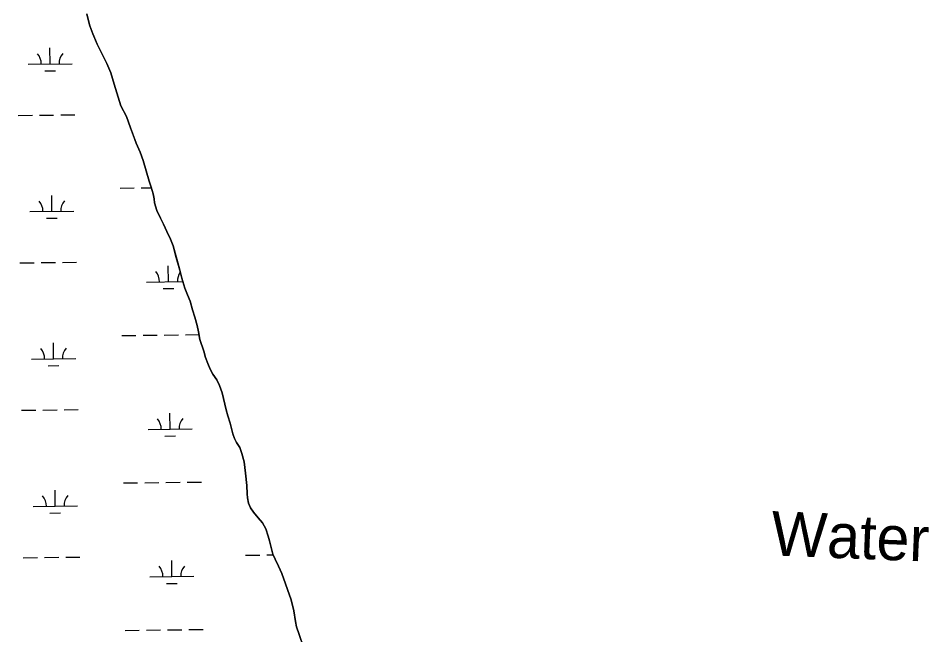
# Model space of a CAD drawing. Extents: x 3678539 to 3716648, y 451386 to 477139.
# Drawn here: x 3688551 to 3690606, y 458475 to 459867 of the extents above; entities that cross this region are included whole.
import ezdxf

# ---------------------------------------------------------------- set-up
doc = ezdxf.new("R2010")
doc.units = 0
for name, color, linetype in [('V-RIVR-IDEN', 7, 'Continuous'), ('V-TOPO-SHOR', 7, 'Continuous'), ('V-WETL-SWMP', 7, 'Continuous')]:
    doc.layers.add(name, color=color, linetype=linetype)

msp = doc.modelspace()

# ---------------------------------------------------------------- linework, layer by layer
at = {"layer": 'V-TOPO-SHOR'}
msp.add_lwpolyline([(3689195.2, 458447.5), (3689185, 458476.1), (3689179.4, 458493), (3689176.6, 458505), (3689173.4, 458529.2), (3689167.4, 458553.9), (3689146, 458613.5), (3689138.6, 458630.1), (3689130.7, 458645.8), (3689125.6, 458657.2), (3689120.8, 458675.4), (3689118.3, 458687.4), (3689115.3, 458697.8), (3689109.7, 458714.5), (3689102.5, 458728), (3689092.2, 458739.5), (3689081.9, 458751.8), (3689075.2, 458761.7), (3689070.9, 458772.1), (3689068.1, 458784.1), (3689067.9, 458793.4), (3689066.8, 458812.4), (3689063.6, 458839.9), (3689061.2, 458865.9), (3689055.9, 458884.6), (3689050.8, 458897.9), (3689043.6, 458909.4), (3689039.3, 458918.2), (3689035.2, 458929.2), (3689032.7, 458941.1), (3689029.4, 458952.8), (3689024.1, 458969.8), (3689020.5, 458982.8), (3689011.2, 459021.5), (3689004.9, 459037.9), (3688999, 459050.7), (3688990.2, 459063.5), (3688984.4, 459074.4), (3688978.7, 459087.2), (3688973.9, 459101), (3688969.6, 459115.5), (3688961, 459141.8), (3688957.7, 459159), (3688954.7, 459173), (3688949.7, 459192.3), (3688944.3, 459208.9), (3688938.8, 459227.9), (3688933.4, 459242.2), (3688927.3, 459257.8), (3688919.9, 459280.2), (3688915.4, 459298.2), (3688906.3, 459331.7), (3688900.5, 459353.3), (3688894.9, 459368.4), (3688886.7, 459385.6), (3688878.8, 459402), (3688872.1, 459415.3), (3688863.7, 459433), (3688858.6, 459450.2), (3688857.7, 459458.8), (3688855.7, 459470.7), (3688851.1, 459485.5), (3688846.3, 459498.8), (3688832.6, 459545.6), (3688826, 459564.1), (3688817.1, 459584.4), (3688810.2, 459603.7), (3688804.6, 459619.6), (3688795.4, 459644.6), (3688782.4, 459669.1), (3688767.2, 459718), (3688759.6, 459743.2), (3688750.6, 459764.3), (3688742, 459782.5), (3688728.9, 459808.1), (3688723.6, 459820.8), (3688719, 459831.5), (3688712.3, 459849.7), (3688708.8, 459863.5), (3688705.5, 459876.8)], dxfattribs=at)
at = {"layer": 'V-WETL-SWMP'}
for p, q in [((3688705.5, 459876.8), (3688712.3, 459849.7)), ((3688712.3, 459849.7), (3688719, 459831.5)), ((3688719, 459831.5), (3688728.9, 459808.1)), ((3688622.9, 459763.5), (3688622.5, 459799.5)), ((3688728.9, 459808.1), (3688742, 459782.5)), ((3688742, 459782.5), (3688750.6, 459764.3)), ((3688573, 459762.9), (3688672.9, 459764.1)), ((3688611.1, 459748), (3688635.1, 459748.2)), ((3688750.6, 459764.3), (3688759.6, 459743.2)), ((3688759.6, 459743.2), (3688767.2, 459718)), ((3688767.2, 459718), (3688782.4, 459669.1)), ((3688782.4, 459669.1), (3688795.4, 459644.6)), ((3688550.9, 459647.3), (3688582.9, 459647.6)), ((3688598.9, 459647.8), (3688630.9, 459648.2)), ((3688646.9, 459648.4), (3688678.9, 459648.7)), ((3688795.4, 459644.6), (3688804.6, 459619.6)), ((3688804.6, 459619.6), (3688817.1, 459584.4)), ((3688817.1, 459584.4), (3688826, 459564.1)), ((3688826, 459564.1), (3688832.6, 459545.6)), ((3688832.6, 459545.6), (3688846.3, 459498.8)), ((3688780.8, 459483.4), (3688812.8, 459483.7)), ((3688828.8, 459483.9), (3688851.5, 459484.2)), ((3688846.3, 459498.8), (3688851.1, 459485.5)), ((3688851.1, 459485.5), (3688855.7, 459470.7)), ((3688626.8, 459430.9), (3688626.4, 459466.9)), ((3688855.7, 459470.7), (3688857.7, 459458.8)), ((3688857.7, 459458.8), (3688858.6, 459450.2)), ((3688858.6, 459450.2), (3688863.7, 459433)), ((3688576.8, 459430.3), (3688676.8, 459431.4)), ((3688863.7, 459433), (3688872.1, 459415.3)), ((3688614.9, 459415.3), (3688638.9, 459415.6)), ((3688872.1, 459415.3), (3688878.8, 459402)), ((3688878.8, 459402), (3688886.7, 459385.6)), ((3688886.7, 459385.6), (3688894.9, 459368.4)), ((3688894.9, 459368.4), (3688900.5, 459353.3)), ((3688900.5, 459353.3), (3688915.4, 459298.2)), ((3688650.7, 459315.7), (3688682.7, 459316.1)), ((3688554.7, 459314.6), (3688586.7, 459315)), ((3688602.7, 459315.1), (3688634.7, 459315.5)), ((3688890.1, 459272), (3688889.6, 459308)), ((3688915.4, 459298.2), (3688919.9, 459280.2)), ((3688919.9, 459280.2), (3688927.3, 459257.8)), ((3688840.1, 459271.4), (3688922.5, 459272.4)), ((3688878.2, 459256.5), (3688902.2, 459256.7)), ((3688927.3, 459257.8), (3688933.4, 459242.2)), ((3688933.4, 459242.2), (3688938.8, 459227.9)), ((3688938.8, 459227.9), (3688944.3, 459208.9)), ((3688944.3, 459208.9), (3688949.7, 459192.3)), ((3688949.7, 459192.3), (3688954.7, 459173)), ((3688954.7, 459173), (3688957.7, 459159)), ((3688832.6, 459151.3), (3688864.6, 459151.6)), ((3688880.6, 459151.8), (3688912.6, 459152.2)), ((3688928.6, 459152.4), (3688958.9, 459152.7)), ((3688957.7, 459159), (3688961, 459141.8)), ((3688630.6, 459098.2), (3688630.2, 459134.2)), ((3688784.6, 459150.7), (3688816.6, 459151.1)), ((3688961, 459141.8), (3688969.6, 459115.5)), ((3688969.6, 459115.5), (3688973.9, 459101)), ((3688580.6, 459097.6), (3688680.6, 459098.8)), ((3688973.9, 459101), (3688978.7, 459087.2)), ((3688618.8, 459082.6), (3688642.8, 459082.9)), ((3688978.7, 459087.2), (3688984.4, 459074.4)), ((3688984.4, 459074.4), (3688990.2, 459063.5)), ((3688990.2, 459063.5), (3688999, 459050.7)), ((3688999, 459050.7), (3689004.9, 459037.9)), ((3689004.9, 459037.9), (3689011.2, 459021.5)), ((3689011.2, 459021.5), (3689020.5, 458982.8)), ((3688558.5, 458981.9), (3688590.5, 458982.3)), ((3688606.5, 458982.5), (3688638.5, 458982.9)), ((3688654.5, 458983), (3688686.5, 458983.4)), ((3688893.9, 458939.4), (3688893.5, 458975.4)), ((3689020.5, 458982.8), (3689024.1, 458969.8)), ((3689024.1, 458969.8), (3689029.4, 458952.8)), ((3689029.4, 458952.8), (3689032.7, 458941.1)), ((3688843.9, 458938.8), (3688943.9, 458939.9)), ((3689032.7, 458941.1), (3689035.2, 458929.2)), ((3689035.2, 458929.2), (3689039.3, 458918.2)), ((3688882.1, 458923.8), (3688906, 458924.1)), ((3689039.3, 458918.2), (3689043.6, 458909.4)), ((3689043.6, 458909.4), (3689050.8, 458897.9)), ((3689050.8, 458897.9), (3689055.9, 458884.6)), ((3689055.9, 458884.6), (3689061.2, 458865.9)), ((3689061.2, 458865.9), (3689063.6, 458839.9)), ((3689063.6, 458839.9), (3689066.8, 458812.4)), ((3688788.4, 458818.1), (3688820.4, 458818.4)), ((3688836.4, 458818.6), (3688868.4, 458819)), ((3688884.4, 458819.2), (3688916.4, 458819.5)), ((3688932.4, 458819.7), (3688964.4, 458820.1)), ((3689066.8, 458812.4), (3689067.9, 458793.4)), ((3688634.4, 458765.6), (3688634, 458801.6)), ((3689067.9, 458793.4), (3689068.1, 458784.1)), ((3689068.1, 458784.1), (3689070.9, 458772.1)), ((3688584.4, 458765), (3688684.4, 458766.1)), ((3689070.9, 458772.1), (3689075.2, 458761.7)), ((3689075.2, 458761.7), (3689081.9, 458751.8)), ((3688622.6, 458750), (3688646.6, 458750.3)), ((3689081.9, 458751.8), (3689092.2, 458739.5)), ((3689092.2, 458739.5), (3689102.5, 458728)), ((3689102.5, 458728), (3689109.7, 458714.5)), ((3689109.7, 458714.5), (3689115.3, 458697.8)), ((3689115.3, 458697.8), (3689118.3, 458687.4)), ((3689118.3, 458687.4), (3689120.8, 458675.4)), ((3689120.8, 458675.4), (3689125.6, 458657.2)), ((3688562.3, 458649.3), (3688594.3, 458649.7)), ((3688610.3, 458649.8), (3688642.3, 458650.2)), ((3688658.3, 458650.4), (3688690.3, 458650.8)), ((3688897.7, 458606.7), (3688897.3, 458642.7)), ((3689064.2, 458655.1), (3689096.2, 458655.4)), ((3689112.2, 458655.6), (3689126.2, 458655.8)), ((3689125.6, 458657.2), (3689130.7, 458645.8)), ((3689130.7, 458645.8), (3689138.6, 458630.1)), ((3689138.6, 458630.1), (3689146, 458613.5)), ((3688847.7, 458606.1), (3688947.7, 458607.3)), ((3689146, 458613.5), (3689167.4, 458553.9)), ((3688885.9, 458591.1), (3688909.9, 458591.4)), ((3689167.4, 458553.9), (3689173.4, 458529.2)), ((3689173.4, 458529.2), (3689176.6, 458505)), ((3689176.6, 458505), (3689179.4, 458493)), ((3688792.2, 458485.4), (3688824.2, 458485.8)), ((3688840.2, 458486), (3688872.2, 458486.3)), ((3688888.2, 458486.5), (3688920.2, 458486.9)), ((3688936.2, 458487.1), (3688968.2, 458487.4)), ((3689179.4, 458493), (3689185, 458476.1)), ((3689185, 458476.1), (3689195.2, 458447.5))]:
    msp.add_line(p, q, dxfattribs=at)
for centre, start, end in [((3688567.7, 459763.4), 359.8865, 41.4302), ((3688678.2, 459764.6), 139.8865, 181.4302), ((3688571.5, 459430.7), 359.8865, 41.4302), ((3688682, 459432), 139.8865, 181.4302), ((3688834.8, 459271.9), 359.8865, 41.4302), ((3688945.3, 459273.1), 144.5602, 181.4302), ((3688575.3, 459098.1), 359.8865, 41.4302), ((3688685.8, 459099.3), 139.8865, 181.4302), ((3688838.6, 458939.2), 359.8865, 41.4302), ((3688949.1, 458940.5), 139.8865, 181.4302), ((3688579.2, 458765.4), 359.8865, 41.4302), ((3688689.7, 458766.7), 139.8865, 181.4302), ((3688842.5, 458606.6), 359.8865, 41.4302), ((3688952.9, 458607.8), 139.8865, 181.4302)]:
    msp.add_arc(centre, 35.2, start, end, dxfattribs=at)

# ---------------------------------------------------------------- texts
at = {"layer": 'V-RIVR-IDEN'}
msp.add_text('Water', height=100, rotation=357.7236, dxfattribs=at).set_placement((3690249.2, 458654.7))

doc.saveas('drawing.dxf')
